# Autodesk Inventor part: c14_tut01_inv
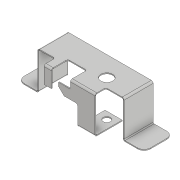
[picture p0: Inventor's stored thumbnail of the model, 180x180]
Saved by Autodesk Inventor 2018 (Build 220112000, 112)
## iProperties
Created: 2015-06
Part Number: c14_tut01_inv
Material: Generic
Document SubType Name: Sheet Metal
Designer: Sandeep
Density: 1 g/cm^3
Sheet Metal Rule: Default_mm
Appearance: Default
Flat Pattern Width: 11.1524 cm
Flat Pattern Length: 21.7129 cm
Flat Pattern Area: 242.15 cm^2
Sheet Metal Width: 111.524 mm
Sheet Metal Length: 217.129 mm
Sheet Metal Area: 24215.030 mm^2
Author: Sandeep
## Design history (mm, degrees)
node "Face1"
  sketch "Sketch1"
    geometry: L1 (0, 12)-(0, 44); L2 (0, 44)-(95, 44); L3 (95, 44)-(95, 12); L4 (95, 12)-(75, 12); L5 (75, 12)-(75, 0); L6 (75, 0)-(48, 0); L7 (48, 0)-(48, 18); L8 (48, 18)-(27, 18); L9 (27, 18)-(27, 0); L10 (27, 0)-(19, 0); L11 (19, 0)-(19, 12); L12 (19, 12)-(0, 12); L13 (0, 0)-(0, 88.508); L14 (0, 0)-(152.255, 0)
    constraints: 28 end point, 11 perpendicular, 4 point on line, 2 vertical, 1 horizontal
    dimensions: "d0" = 26 distance between parallel lines of L2 L8; "d1" = 19 distance between parallel lines of L13 L11; "d2" = 8 distance between parallel lines of L9 L11; "d3" = 32 distance between parallel lines of L12 L2; "d4" = 27 distance between parallel lines of L5 L7; "d5" = 20 distance between parallel lines of L3 L5; "d6" = 95 distance between parallel lines of L1 L3; "d7" = 44 distance between parallel lines of L6 L2
node "Contour Flange1"
node "Contour Flange3"
  sketch "Sketch10"
    geometry: L1 (0, 0)-(41, 0); L2 (41, 0)-(41, 30)
    constraints: 4 end point, 1 horizontal, 1 perpendicular
    dimensions: "d42" = 41 distance of L1.start L1.end; "d43" = 30 distance of L1.end L2.end
sketch "Sketch11"
  geometry: L1 (-3.447, 20)-(8, 20); L2 (8, 20)-(8, -8.777); L3 (8, -8.777)-(-3.447, -8.777); L4 (-3.447, -8.777)-(-3.447, 20); L5 (27, 37)-(27, 0) reference; L6 (0, 39)-(-21, 39) reference; 1 further point
  constraints: 8 end point, 2 parallel, 1 horizontal, 1 perpendicular
  dimensions: "d45" = 19 distance between parallel lines of L5 L2; "d104" = 19 distance between parallel lines of L6 L1
cut "Cut1" sketch "Sketch11" dims "d46" = 1 (= Thickness), "d47" = 0
node "Face2"
  sketch "Sketch12"
    geometry: L1 (0, -17)-(-13, -17); L2 (-13, -17)-(-13, -7); L3 (-13, -7)-(0, -7); L4 (0, 0)-(0, -17) reference; 1 further point
    constraints: 6 end point, 2 perpendicular, 1 horizontal, 1 point on line
    dimensions: "d54" = 13 distance between parallel lines of L2 L4; "d55" = 10 distance of L1.end L2.end
feature "Corner Round1" dims "d56" = 2
feature "Corner Chamfer1" dims "d57" = 6, "d58" = 6, angle "d59" = 45 deg
node "Flange1"
hole "Hole1" diameter "d72" = 13; stored, may be unused: countersink angle "d76" = 90 deg, drill point angle "d78" = 0 deg; dims "d70" = 9, "d71" = 22, "d73" = 6, "d74" = 4, "d75" = 2, "d77" = 1 (= Thickness)
hole "Hole2" diameter "d81" = 8; stored, may be unused: countersink angle "d85" = 90 deg, drill point angle "d87" = 0 deg; dims "d79" = 9, "d80" = 22, "d82" = 6, "d83" = 4, "d84" = 2, "d86" = 1 (= Thickness)
feature "Corner Round2" dims "d88" = 7
workplane "Work Plane1"
node "Contour Flange4"
  sketch "Sketch15"
    geometry: L1 (0, 0.919)-(0, -40.081); L2 (0, -40.081)-(-22, -40.081); 1 further point
    constraints: 4 end point, 1 perpendicular, 1 vertical
    dimensions: "d90" = 41 distance of L1.start L1.end; "d91" = 22 distance of L1.end L2.end
feature "Corner Round4" dims "d101" = 7
feature "Corner Round5" dims "d102" = 2
body "Solid1"
face "Plate1" dims "d103" = 1 (= Thickness)
sketch "Sketch6"
  geometry: L1 (-75, 1)-(20, 1) reference; L2 (20, 1)-(20, -39); L3 (20, -39)-(42, -39); L4 (-75, 1)-(-75, -39); L5 (-75, -39)-(-97, -39); 1 further point
  constraints: 8 end point, 2 perpendicular, 2 vertical
  dimensions: "d9" = 40 distance of L1.end L2.end; "d10" = 22 distance of L2.end L3.end; "d20" = 40 distance of L1.start L4.end
face "Plate2" dims "d11" = 1 (= BendReliefWidth), "d12" = 0.5 (= BendReliefDepth), "d13" = 2 (= MinimumRemnant), "d14" = 1 (= BendRadius), "d15" = 1 (= BendRadius), "d16" = 1, "d17" = 4 (= CornerReliefSize), "d18" = 1 (= GapSize), "d19" = 1 (= JacobiRadiusSize), "d103" = 1 (= Thickness), "SeamGap" = 0.01
bend "Bend1" dims "d11" = 1 (= BendReliefWidth), "d12" = 0.5 (= BendReliefDepth), "d13" = 2 (= MinimumRemnant), "d14" = 1 (= BendRadius), "d15" = 1 (= BendRadius), "d16" = 1, "d103" = 1 (= Thickness), "SeamGap" = 0.01
feature "Corner1" dims "d16" = 1, "d17" = 4 (= CornerReliefSize), "d18" = 1 (= GapSize), "d19" = 1 (= JacobiRadiusSize)
face "Plate4" dims "d33" = 1 (= BendReliefWidth), "d34" = 0.5 (= BendReliefDepth), "d35" = 2 (= MinimumRemnant), "d36" = 1 (= BendRadius), "d37" = 1 (= BendRadius), "d38" = 1, "d39" = 4 (= CornerReliefSize), "d40" = 1 (= GapSize), "d41" = 1 (= JacobiRadiusSize), "d103" = 1 (= Thickness), "SeamGap" = 0.01
bend "Bend3" dims "d33" = 1 (= BendReliefWidth), "d34" = 0.5 (= BendReliefDepth), "d35" = 2 (= MinimumRemnant), "d36" = 1 (= BendRadius), "d37" = 1 (= BendRadius), "d38" = 1, "d103" = 1 (= Thickness), "SeamGap" = 0.01
feature "Corner3" dims "d38" = 1, "d39" = 4 (= CornerReliefSize), "d40" = 1 (= GapSize), "d41" = 1 (= JacobiRadiusSize)
face "Plate5" dims "d49" = 1 (= BendRadius), "d50" = 1 (= BendReliefWidth), "d52" = 2 (= MinimumRemnant), "d103" = 1 (= Thickness)
bend "Bend4" dims "d49" = 1 (= BendRadius), "d50" = 1 (= BendReliefWidth), "d51" = 0.5 (= BendReliefDepth), "d52" = 2 (= MinimumRemnant), "d53" = 1 (= BendRadius), "d103" = 1 (= Thickness), "SeamGap" = 0.01
sketch "Sketch13"
  geometry: L1 through (-4, 0) direction (1, 6.84e-48); L2 through (0, 9.5) direction (-4.87e-32, 1); L3 (0, 19)-(-8, 19); L4 (-8, 19)-(-8, 0)
  constraints: 6 end point, 1 horizontal, 1 perpendicular, 1 vertical
face "Plate6" dims "d60" = 1 (= BendReliefWidth), "d61" = 0.5 (= BendReliefDepth), "d62" = 2 (= MinimumRemnant), "d63" = 1 (= BendRadius), "d64" = 19, "d65" = 90 deg, "d66" = 1 (= BendRadius), "d67" = 4 (= CornerReliefSize), "d68" = 1 (= GapSize), "d69" = 1 (= JacobiRadiusSize), "d103" = 1 (= Thickness), "SeamGap" = 0.01
bend "Bend5" dims "d60" = 1 (= BendReliefWidth), "d61" = 0.5 (= BendReliefDepth), "d62" = 2 (= MinimumRemnant), "d63" = 1 (= BendRadius), "d64" = 19, "d65" = 90 deg, "d66" = 1 (= BendRadius), "d103" = 1 (= Thickness), "SeamGap" = 0.01
feature "Corner4" dims "d64" = 19, "d65" = 90 deg, "d67" = 4 (= CornerReliefSize), "d68" = 1 (= GapSize), "d69" = 1 (= JacobiRadiusSize)
face "Plate7" dims "d92" = 1 (= BendReliefWidth), "d93" = 0.5 (= BendReliefDepth), "d94" = 2 (= MinimumRemnant), "d95" = 1 (= BendRadius), "d96" = 1 (= BendRadius), "d97" = 1, "d98" = 4 (= CornerReliefSize), "d99" = 1 (= GapSize), "d100" = 1 (= JacobiRadiusSize), "d103" = 1 (= Thickness), "SeamGap" = 0.01
bend "Bend6" dims "d92" = 1 (= BendReliefWidth), "d93" = 0.5 (= BendReliefDepth), "d94" = 2 (= MinimumRemnant), "d95" = 1 (= BendRadius), "d96" = 1 (= BendRadius), "d97" = 1, "d103" = 1 (= Thickness), "SeamGap" = 0.01
feature "Corner5" dims "d97" = 1, "d98" = 4 (= CornerReliefSize), "d99" = 1 (= GapSize), "d100" = 1 (= JacobiRadiusSize)
feature "Definition1"
other parameters: "Thickness" = 1 (derived), "BendRadius" = 1 (= Thickness), "BendReliefWidth" = 1 (= Thickness), "BendReliefDepth" = 0.5 (= 0.5 x Thickness), "CornerReliefSize" = 4 (= 4 x Thickness), "MinimumRemnant" = 2 (= 2 x Thickness), "TransitionRadius" = 1 (= BendRadius), "JacobiRadiusSize" = 1 (= BendRadius), "GapSize" = 1 (= Thickness), "d8" = 1 (= BendRadius), "BendRadius" = 1, "BendReliefDepth" = 0.5, "BendReliefWidth" = 1, "CornerReliefSize" = 4, "GapSize" = 1, "JacobiRadiusSize" = 1, "MinimumRemnant" = 2, "Thickness" = 1, "TransitionRadius" = 1
